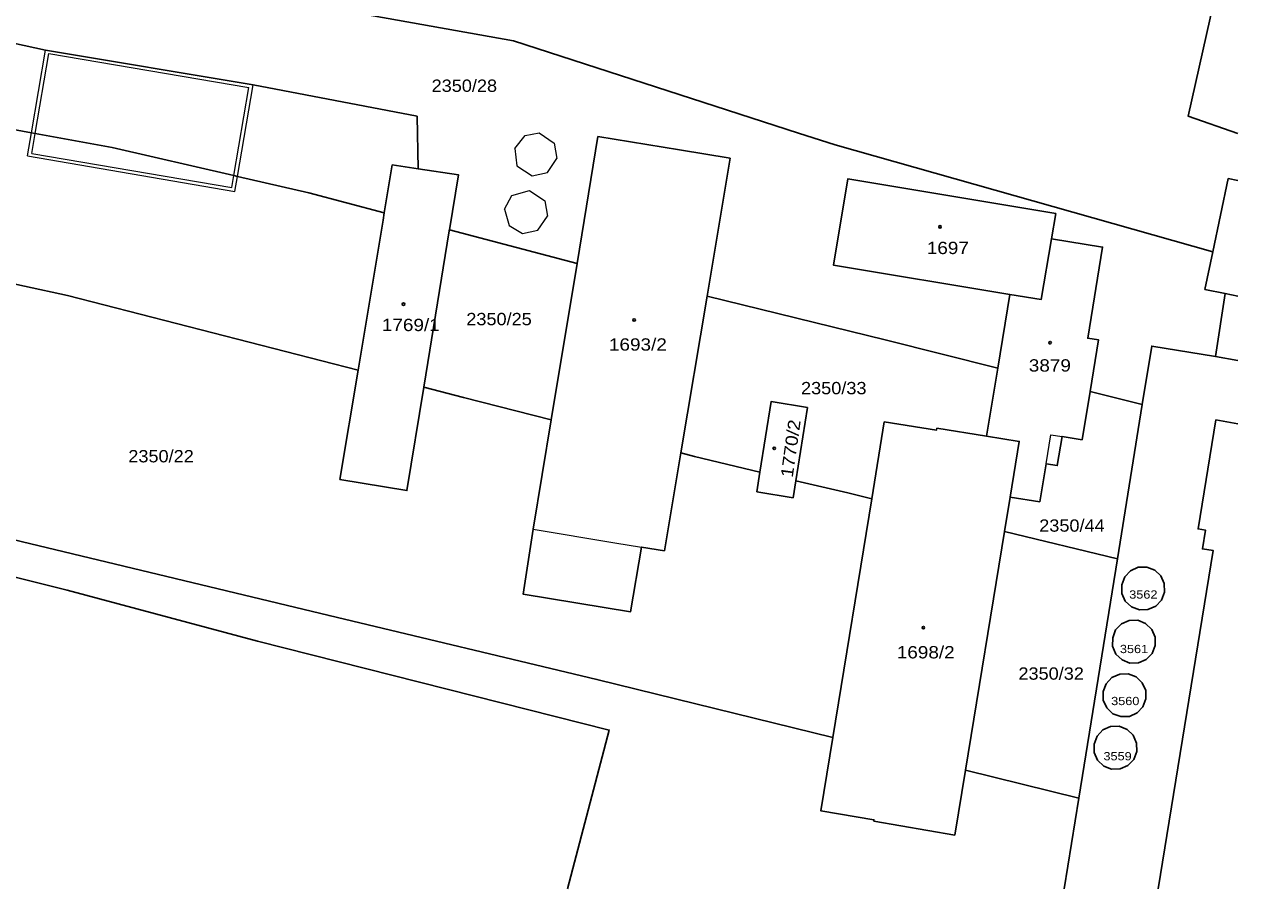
# Model space of a CAD drawing. Extents: x -652394 to -652006, y -1024262 to -1023975.
# Drawn here: x -652176.9 to -652009.4, y -1024262 to -1024142.7 of the extents above; entities that cross this region are included whole.
import ezdxf

# ---------------------------------------------------------------- set-up
doc = ezdxf.new("R2010")
doc.units = 0
doc.header["$LTSCALE"] = 0.46
doc.layers.add('63', color=7, linetype='Continuous', lineweight=25)

msp = doc.modelspace()

# ---------------------------------------------------------------- linework, layer by layer
at = {"layer": '63', "lineweight": 13}
for p, q in [((-652175.94, -1024157.67), (-652173.97, -1024146.26)), ((-652147.5, -1024163.71), (-652145.34, -1024151.05)), ((-652176.49, -1024160.87), (-652175.94, -1024157.67)), ((-652175.9, -1024160.55), (-652175.43, -1024157.76)), ((-652105.85, -1024157.7), (-652103.76, -1024159.11)), ((-652103.76, -1024159.11), (-652103.39, -1024161.24)), ((-652175.9, -1024160.55), (-652148.27, -1024165.24)), ((-652109.22, -1024159.84), (-652108.91, -1024162.22)), ((-652108.91, -1024162.22), (-652106.82, -1024163.63)), ((-652104.69, -1024163.18), (-652103.39, -1024161.24)), ((-652106.82, -1024163.63), (-652104.69, -1024163.18)), ((-652110.62, -1024168.24), (-652109.62, -1024166.34)), ((-652105.08, -1024167.05), (-652104.7, -1024169.17)), ((-652106.01, -1024171.12), (-652104.7, -1024169.17))]:
    msp.add_line(p, q, dxfattribs=at)
at = {"layer": '63'}
for p, q in [((-652145.34, -1024151.05), (-652173.97, -1024146.26)), ((-652100.61, -1024175.7), (-652097.72, -1024158.21)), ((-652079.47, -1024161.16), (-652082.66, -1024180.25)), ((-652010.71, -1024163.99), (-652009.403, -1024164.271)), ((-652100.61, -1024175.7), (-652118.23, -1024171.08)), ((-652100.61, -1024175.7), (-652104.17, -1024197.29)), ((-652082.66, -1024180.25), (-652086.28, -1024201.86)), ((-652042.54, -1024190.17), (-652040.87, -1024179.99)), ((-652012.46, -1024188.58), (-652011.13, -1024179.88)), ((-652009.403, -1024180.239), (-652011.13, -1024179.88)), ((-652009.403, -1024189.091), (-652012.46, -1024188.58)), ((-652044.08, -1024199.55), (-652042.54, -1024190.17)), ((-652029.78, -1024193.37), (-652030.87, -1024200.07)), ((-652070.39, -1024205.73), (-652068.81, -1024195.59)), ((-652106.67, -1024212.4), (-652104.17, -1024197.29)), ((-652044.08, -1024199.55), (-652050.95, -1024198.45)), ((-652086.28, -1024201.86), (-652088.54, -1024215.36)), ((-652075.79, -1024207.24), (-652075.36, -1024204.52)), ((-652070.39, -1024205.73), (-652070.76, -1024208.08)), ((-652070.76, -1024208.08), (-652075.79, -1024207.24)), ((-652041.6, -1024212.7), (-652040.83, -1024207.98)), ((-652059.93, -1024208.21), (-652065.32, -1024241.16)), ((-652026.02, -1024216.47), (-652041.6, -1024212.7)), ((-652026.02, -1024216.47), (-652031.36, -1024249.53)), ((-652048.47, -1024254.62), (-652046.99, -1024245.67)), ((-652031.36, -1024249.53), (-652033.378, -1024262.022)), ((-652059.65, -1024252.69), (-652048.47, -1024254.62))]:
    msp.add_line(p, q, dxfattribs=at)
for points in [[(-652009.403, -1024157.766), (-652016.24, -1024155.4), (-652012.21, -1024137.29), (-652009.403, -1024126.324)], [(-652198.26, -1024128.72), (-652174.89, -1024133.55), (-652133.42, -1024140.71), (-652109.38, -1024144.99), (-652070.02, -1024157.71), (-652064.99, -1024159.32), (-652012.85, -1024174.11)], [(-652173.97, -1024146.26), (-652200.37, -1024140.5), (-652219.59, -1024137.03), (-652250.2, -1024132.43)], [(-652251.83, -1024144.08), (-652237.23, -1024146.17), (-652218.01, -1024149.63), (-652190.61, -1024154.99), (-652175.94, -1024157.67), (-652175.43, -1024157.76), (-652164.78, -1024159.71), (-652147.99, -1024163.59), (-652147.5, -1024163.71), (-652137.65, -1024165.98), (-652127.22, -1024168.72)], [(-652122.53, -1024162.65), (-652122.69, -1024155.4), (-652145.34, -1024151.05)], [(-652097.72, -1024158.21), (-652086.46, -1024160.03), (-652079.47, -1024161.16)], [(-652127.22, -1024168.72), (-652126.12, -1024162.11), (-652122.53, -1024162.65)], [(-652122.53, -1024162.65), (-652116.99, -1024163.48), (-652118.23, -1024171.08)], [(-652259.41, -1024164.46), (-652231.87, -1024168.37), (-652206.61, -1024172.41), (-652170.95, -1024180.16), (-652130.83, -1024190.46), (-652133.34, -1024205.54)], [(-652040.87, -1024179.99), (-652065.2, -1024175.97), (-652063.24, -1024164.04), (-652034.52, -1024168.83), (-652035.12, -1024172.31)], [(-652011.13, -1024179.88), (-652013.94, -1024179.29), (-652012.85, -1024174.11), (-652010.71, -1024163.99)], [(-652130.83, -1024190.46), (-652127.39, -1024169.76), (-652127.22, -1024168.72)], [(-652118.23, -1024171.08), (-652118.25, -1024171.19), (-652121.77, -1024192.79)], [(-652035.12, -1024172.31), (-652036.55, -1024180.7), (-652040.87, -1024179.99)], [(-652035.12, -1024172.31), (-652028.05, -1024173.46), (-652030.11, -1024186.04), (-652028.62, -1024186.28), (-652029.78, -1024193.37), (-652022.58, -1024195.17)], [(-652082.66, -1024180.25), (-652058.09, -1024186.27), (-652042.54, -1024190.17)], [(-652012.46, -1024188.58), (-652021.28, -1024187.11), (-652022.58, -1024195.17), (-652026.02, -1024216.47)], [(-652133.34, -1024205.54), (-652124.1, -1024207.07), (-652121.77, -1024192.79)], [(-652104.17, -1024197.29), (-652116.27, -1024194.21), (-652121.77, -1024192.79)], [(-652264.55, -1024196.15), (-652231.24, -1024202.08), (-652184.5, -1024212.41), (-652134.85, -1024224.32), (-652097.87, -1024233.14), (-652065.32, -1024241.16)], [(-652068.81, -1024195.59), (-652073.83, -1024194.79), (-652075.36, -1024204.52)], [(-652050.95, -1024198.45), (-652051, -1024198.73), (-652058.2, -1024197.59), (-652059.93, -1024208.21)], [(-652020.396, -1024262.022), (-652012.78, -1024215.35), (-652014.27, -1024215.11), (-652013.85, -1024212.53), (-652014.87, -1024212.36), (-652012.41, -1024197.3), (-652009.403, -1024197.839)], [(-652036.73, -1024208.64), (-652040.83, -1024207.98), (-652039.57, -1024200.28), (-652044.08, -1024199.55)], [(-652030.87, -1024200.07), (-652033.65, -1024199.6), (-652034.31, -1024203.62), (-652035.86, -1024203.38), (-652036.73, -1024208.64)], [(-652101.939, -1024262.022), (-652096.17, -1024240.13), (-652144.74, -1024227.85), (-652171.01, -1024220.79), (-652209.63, -1024211.21), (-652248.76, -1024203.78), (-652265.35, -1024201.09)], [(-652075.36, -1024204.52), (-652084.39, -1024202.34), (-652086.28, -1024201.86)], [(-652059.93, -1024208.21), (-652063.22, -1024207.39), (-652070.39, -1024205.73)], [(-652088.54, -1024215.36), (-652091.72, -1024214.86), (-652093.22, -1024223.79), (-652108.04, -1024221.38), (-652106.67, -1024212.4)], [(-652031.36, -1024249.53), (-652046.99, -1024245.67), (-652041.6, -1024212.7)], [(-652065.32, -1024241.16), (-652066.97, -1024251.27), (-652059.62, -1024252.49), (-652059.65, -1024252.69)]]:
    msp.add_lwpolyline(points, dxfattribs=at)
at = {"layer": '63', "lineweight": 13}
for points in [[(-652122.53, -1024162.65), (-652122.69, -1024155.4), (-652145.34, -1024151.05), (-652173.97, -1024146.26), (-652200.37, -1024140.5), (-652219.59, -1024137.03), (-652250.2, -1024132.43), (-652251.83, -1024144.08), (-652237.23, -1024146.17), (-652218.01, -1024149.63), (-652190.61, -1024154.99), (-652175.94, -1024157.67), (-652175.43, -1024157.76), (-652164.78, -1024159.71), (-652147.99, -1024163.59), (-652147.5, -1024163.71), (-652137.65, -1024165.98), (-652127.22, -1024168.72), (-652126.12, -1024162.11)], [(-652251.83, -1024144.08), (-652253.01, -1024152.48), (-652257.95, -1024151.77), (-652258.61, -1024159.53), (-652259.41, -1024164.46), (-652231.87, -1024168.37), (-652206.61, -1024172.41), (-652170.95, -1024180.16), (-652130.83, -1024190.46), (-652127.39, -1024169.76), (-652127.22, -1024168.72), (-652137.65, -1024165.98), (-652147.5, -1024163.71), (-652147.99, -1024163.59), (-652164.78, -1024159.71), (-652175.43, -1024157.76), (-652175.94, -1024157.67), (-652190.61, -1024154.99), (-652218.01, -1024149.63), (-652237.23, -1024146.17)], [(-652104.17, -1024197.29), (-652106.67, -1024212.4), (-652108.04, -1024221.38), (-652093.22, -1024223.79), (-652091.72, -1024214.86), (-652088.54, -1024215.36), (-652086.28, -1024201.86), (-652082.66, -1024180.25), (-652079.47, -1024161.16), (-652086.46, -1024160.03), (-652097.72, -1024158.21), (-652100.61, -1024175.7)], [(-652106.67, -1024212.4), (-652095.41, -1024214.29), (-652091.72, -1024214.86), (-652088.54, -1024215.36), (-652086.28, -1024201.86), (-652082.66, -1024180.25), (-652079.47, -1024161.16), (-652086.46, -1024160.03), (-652097.72, -1024158.21), (-652100.61, -1024175.7), (-652104.17, -1024197.29)], [(-652121.77, -1024192.79), (-652118.25, -1024171.19), (-652118.23, -1024171.08), (-652116.99, -1024163.48), (-652122.53, -1024162.65), (-652126.12, -1024162.11), (-652127.22, -1024168.72), (-652127.39, -1024169.76), (-652130.83, -1024190.46), (-652133.34, -1024205.54), (-652124.1, -1024207.07)], [(-652127.39, -1024169.76), (-652130.83, -1024190.46), (-652133.34, -1024205.54), (-652124.1, -1024207.07), (-652121.77, -1024192.79), (-652118.25, -1024171.19), (-652118.23, -1024171.08), (-652116.99, -1024163.48), (-652122.53, -1024162.65), (-652126.12, -1024162.11), (-652127.22, -1024168.72)], [(-652035.12, -1024172.31), (-652034.52, -1024168.83), (-652063.24, -1024164.04), (-652065.2, -1024175.97), (-652040.87, -1024179.99), (-652036.55, -1024180.7)], [(-652065.2, -1024175.97), (-652040.87, -1024179.99), (-652036.55, -1024180.7), (-652035.12, -1024172.31), (-652034.52, -1024168.83), (-652063.24, -1024164.04)], [(-652118.25, -1024171.19), (-652121.77, -1024192.79), (-652116.27, -1024194.21), (-652104.17, -1024197.29), (-652100.61, -1024175.7), (-652118.23, -1024171.08)], [(-652036.55, -1024180.7), (-652040.87, -1024179.99), (-652042.54, -1024190.17), (-652044.08, -1024199.55), (-652039.57, -1024200.28), (-652040.83, -1024207.98), (-652036.73, -1024208.64), (-652035.86, -1024203.38), (-652034.31, -1024203.62), (-652033.65, -1024199.6), (-652030.87, -1024200.07), (-652029.78, -1024193.37), (-652028.62, -1024186.28), (-652030.11, -1024186.04), (-652028.05, -1024173.46), (-652035.12, -1024172.31)], [(-652044.08, -1024199.55), (-652039.57, -1024200.28), (-652040.83, -1024207.98), (-652036.73, -1024208.64), (-652035.86, -1024203.38), (-652035.21, -1024199.35), (-652033.65, -1024199.6), (-652030.87, -1024200.07), (-652029.78, -1024193.37), (-652028.62, -1024186.28), (-652030.11, -1024186.04), (-652028.05, -1024173.46), (-652035.12, -1024172.31), (-652036.55, -1024180.7), (-652040.87, -1024179.99), (-652042.54, -1024190.17)], [(-652082.66, -1024180.25), (-652086.28, -1024201.86), (-652084.39, -1024202.34), (-652075.36, -1024204.52), (-652073.83, -1024194.79), (-652068.81, -1024195.59), (-652070.39, -1024205.73), (-652063.22, -1024207.39), (-652059.93, -1024208.21), (-652058.2, -1024197.59), (-652051, -1024198.73), (-652050.95, -1024198.45), (-652044.08, -1024199.55), (-652042.54, -1024190.17), (-652058.09, -1024186.27)], [(-652033.65, -1024199.6), (-652034.31, -1024203.62), (-652035.86, -1024203.38), (-652036.73, -1024208.64), (-652040.83, -1024207.98), (-652041.6, -1024212.7), (-652026.02, -1024216.47), (-652022.58, -1024195.17), (-652029.78, -1024193.37), (-652030.87, -1024200.07)], [(-652068.81, -1024195.59), (-652073.83, -1024194.79), (-652075.36, -1024204.52), (-652075.79, -1024207.24), (-652070.76, -1024208.08), (-652070.39, -1024205.73)], [(-652075.79, -1024207.24), (-652070.76, -1024208.08), (-652070.39, -1024205.73), (-652068.81, -1024195.59), (-652073.83, -1024194.79), (-652075.36, -1024204.52)], [(-652059.62, -1024252.49), (-652059.65, -1024252.69), (-652048.47, -1024254.62), (-652046.99, -1024245.67), (-652041.6, -1024212.7), (-652040.83, -1024207.98), (-652039.57, -1024200.28), (-652044.08, -1024199.55), (-652050.95, -1024198.45), (-652051, -1024198.73), (-652058.2, -1024197.59), (-652059.93, -1024208.21), (-652065.32, -1024241.16), (-652066.97, -1024251.27)], [(-652041.6, -1024212.7), (-652040.83, -1024207.98), (-652039.57, -1024200.28), (-652044.08, -1024199.55), (-652050.95, -1024198.45), (-652051, -1024198.73), (-652058.2, -1024197.59), (-652059.93, -1024208.21), (-652065.32, -1024241.16), (-652066.97, -1024251.27), (-652059.62, -1024252.49), (-652059.65, -1024252.69), (-652048.47, -1024254.62), (-652046.99, -1024245.67)], [(-652026.02, -1024216.47), (-652041.6, -1024212.7), (-652046.99, -1024245.67), (-652031.36, -1024249.53)], [(-652025.39, -1024220.08), (-652025.39, -1024221.25), (-652024.92, -1024222.31), (-652024.07, -1024223.12), (-652022.97, -1024223.54), (-652021.8, -1024223.5), (-652020.73, -1024223.03), (-652019.93, -1024222.18), (-652019.51, -1024221.08), (-652019.54, -1024219.91), (-652020.02, -1024218.84), (-652020.87, -1024218.04), (-652021.96, -1024217.62), (-652023.13, -1024217.65), (-652024.2, -1024218.13), (-652025.01, -1024218.98)], [(-652023.11, -1024230.85), (-652022.04, -1024230.39), (-652021.22, -1024229.55), (-652020.79, -1024228.46), (-652020.81, -1024227.29), (-652021.28, -1024226.22), (-652022.12, -1024225.4), (-652023.21, -1024224.97), (-652024.38, -1024224.99), (-652025.45, -1024225.46), (-652026.27, -1024226.3), (-652026.65, -1024227.39), (-652026.68, -1024228.56), (-652026.21, -1024229.63), (-652025.37, -1024230.44), (-652024.28, -1024230.87)], [(-652024.36, -1024238.24), (-652023.29, -1024237.76), (-652022.49, -1024236.91), (-652022.07, -1024235.81), (-652022.11, -1024234.64), (-652022.59, -1024233.58), (-652023.44, -1024232.77), (-652024.53, -1024232.36), (-652025.7, -1024232.39), (-652026.77, -1024232.87), (-652027.57, -1024233.72), (-652027.97, -1024234.82), (-652027.96, -1024235.98), (-652027.48, -1024237.05), (-652026.63, -1024237.86), (-652025.53, -1024238.27)], [(-652028.02, -1024240.11), (-652028.83, -1024240.95), (-652029.2, -1024242.05), (-652029.22, -1024243.21), (-652028.75, -1024244.28), (-652027.9, -1024245.09), (-652026.81, -1024245.52), (-652025.64, -1024245.49), (-652024.57, -1024245.01), (-652023.76, -1024244.17), (-652023.34, -1024243.08), (-652023.36, -1024241.91), (-652023.84, -1024240.84), (-652024.68, -1024240.03), (-652025.78, -1024239.6), (-652026.95, -1024239.63)]]:
    msp.add_lwpolyline(points, close=True, dxfattribs=at)
for points in [[(-652200.37, -1024140.5), (-652173.97, -1024146.26), (-652145.34, -1024151.05), (-652122.69, -1024155.4), (-652122.53, -1024162.65), (-652116.99, -1024163.48), (-652118.23, -1024171.08), (-652100.61, -1024175.7), (-652097.72, -1024158.21), (-652086.46, -1024160.03), (-652079.47, -1024161.16), (-652082.66, -1024180.25), (-652058.09, -1024186.27), (-652042.54, -1024190.17), (-652040.87, -1024179.99), (-652065.2, -1024175.97), (-652063.24, -1024164.04), (-652034.52, -1024168.83), (-652035.12, -1024172.31), (-652028.05, -1024173.46), (-652030.11, -1024186.04), (-652028.62, -1024186.28), (-652029.78, -1024193.37), (-652022.58, -1024195.17), (-652021.28, -1024187.11), (-652012.46, -1024188.58), (-652011.13, -1024179.88), (-652013.94, -1024179.29), (-652012.85, -1024174.11), (-652064.99, -1024159.32), (-652070.02, -1024157.71), (-652109.38, -1024144.99), (-652133.42, -1024140.71)], [(-652175.43, -1024157.76), (-652173.55, -1024146.74), (-652145.93, -1024151.42)], [(-652148.27, -1024165.24), (-652147.99, -1024163.59), (-652145.93, -1024151.42)], [(-652109.22, -1024159.84), (-652107.79, -1024158.03), (-652105.85, -1024157.7)], [(-652176.49, -1024160.87), (-652147.85, -1024165.76), (-652147.5, -1024163.71)], [(-652109.62, -1024166.34), (-652107.16, -1024165.64), (-652105.08, -1024167.05)], [(-652110.62, -1024168.24), (-652109.98, -1024170.49), (-652108.13, -1024171.56), (-652106.01, -1024171.12)], [(-652184.5, -1024212.41), (-652134.85, -1024224.32), (-652097.87, -1024233.14), (-652065.32, -1024241.16), (-652059.93, -1024208.21), (-652063.22, -1024207.39), (-652070.39, -1024205.73), (-652070.76, -1024208.08), (-652075.79, -1024207.24), (-652075.36, -1024204.52), (-652084.39, -1024202.34), (-652086.28, -1024201.86), (-652088.54, -1024215.36), (-652091.72, -1024214.86), (-652093.22, -1024223.79), (-652108.04, -1024221.38), (-652106.67, -1024212.4), (-652104.17, -1024197.29), (-652116.27, -1024194.21), (-652121.77, -1024192.79), (-652124.1, -1024207.07), (-652133.34, -1024205.54), (-652130.83, -1024190.46), (-652170.95, -1024180.16), (-652206.61, -1024172.41)], [(-652035.86, -1024203.38), (-652035.21, -1024199.35), (-652033.65, -1024199.6)], [(-652106.67, -1024212.4), (-652095.41, -1024214.29), (-652091.72, -1024214.86)]]:
    msp.add_lwpolyline(points, dxfattribs=at)
at = {"layer": '63'}
for points in [[(-652025.39, -1024220.08), (-652025.01, -1024218.98), (-652024.2, -1024218.13), (-652023.13, -1024217.65), (-652021.96, -1024217.62), (-652020.87, -1024218.04), (-652020.02, -1024218.84), (-652019.54, -1024219.91), (-652019.51, -1024221.08), (-652019.93, -1024222.18), (-652020.73, -1024223.03), (-652021.8, -1024223.5), (-652022.97, -1024223.54), (-652024.07, -1024223.12), (-652024.92, -1024222.31), (-652025.39, -1024221.25)], [(-652023.11, -1024230.85), (-652024.28, -1024230.87), (-652025.37, -1024230.44), (-652026.21, -1024229.63), (-652026.68, -1024228.56), (-652026.65, -1024227.39), (-652026.27, -1024226.3), (-652025.45, -1024225.46), (-652024.38, -1024224.99), (-652023.21, -1024224.97), (-652022.12, -1024225.4), (-652021.28, -1024226.22), (-652020.81, -1024227.29), (-652020.79, -1024228.46), (-652021.22, -1024229.55), (-652022.04, -1024230.39)], [(-652024.36, -1024238.24), (-652025.53, -1024238.27), (-652026.63, -1024237.86), (-652027.48, -1024237.05), (-652027.96, -1024235.98), (-652027.97, -1024234.82), (-652027.57, -1024233.72), (-652026.77, -1024232.87), (-652025.7, -1024232.39), (-652024.53, -1024232.36), (-652023.44, -1024232.77), (-652022.59, -1024233.58), (-652022.11, -1024234.64), (-652022.07, -1024235.81), (-652022.49, -1024236.91), (-652023.29, -1024237.76)], [(-652028.02, -1024240.11), (-652026.95, -1024239.63), (-652025.78, -1024239.6), (-652024.68, -1024240.03), (-652023.84, -1024240.84), (-652023.36, -1024241.91), (-652023.34, -1024243.08), (-652023.76, -1024244.17), (-652024.57, -1024245.01), (-652025.64, -1024245.49), (-652026.81, -1024245.52), (-652027.9, -1024245.09), (-652028.75, -1024244.28), (-652029.22, -1024243.21), (-652029.2, -1024242.05), (-652028.83, -1024240.95)]]:
    msp.add_lwpolyline(points, close=True, dxfattribs=at)
for centre in [(-652050.5068, -1024170.6592), (-652124.5768, -1024181.3392), (-652092.7168, -1024183.5192), (-652035.3068, -1024186.6592), (-652073.3868, -1024201.2392), (-652052.7968, -1024225.9892)]:
    msp.add_circle(centre, 0.175, dxfattribs=at)

# ---------------------------------------------------------------- texts
for s, height, width, p in [('2350/28', 1.7, 1.1, (-652120.69, -1024152.03)), ('1697', 1.7, 1.15, (-652052.33, -1024174.42)), ('2350/25', 1.7, 1.1, (-652115.9, -1024184.24)), ('1769/1', 1.7, 1.15, (-652127.56, -1024185.05)), ('1693/2', 1.7, 1.15, (-652096.21, -1024187.75)), ('3879', 1.7, 1.15, (-652038.247, -1024190.64)), ('2350/33', 1.7, 1.1, (-652069.69, -1024193.77)), ('2350/22', 1.7, 1.1, (-652162.56, -1024203.17)), ('2350/44', 1.7, 1.1, (-652036.808, -1024212.74)), ('3562', 1.139, 1.15, (-652024.379, -1024221.979)), ('1698/2', 1.7, 1.15, (-652056.475, -1024230.23)), ('3561', 1.139, 1.15, (-652025.669, -1024229.499)), ('2350/32', 1.7, 1.1, (-652039.68, -1024233.17)), ('3560', 1.139, 1.15, (-652026.879, -1024236.679)), ('3559', 1.139, 1.15, (-652027.939, -1024244.299))]:
    msp.add_text(s, height=height, dxfattribs=dict(at, width=width)).set_placement(p)
at = {"layer": '63', "width": 1.15}
msp.add_text('1770/2', height=1.7, rotation=82, dxfattribs=at).set_placement((-652070.838, -1024205.328))

doc.saveas('drawing.dxf')
